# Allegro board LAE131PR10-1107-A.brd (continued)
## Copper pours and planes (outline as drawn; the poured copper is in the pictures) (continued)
GPU_B+ on BOTTOM (solid shape): 66.23,74.45 66.23,71.84 65.92,71.52 65.92,70.03 65.85,69.97 65.08,69.97 64.96,70.08 64.96,70.69 64.75,70.91 63.3,70.91 62.23,71.98 59.31,71.98 59.06,72.23 59.06,72.74 59.31,72.99 59.5,72.99 59.82,72.79 60.14,72.99 60.45,72.99 61.25,73.79 61.31,73.79 61.84,74.31 64.52,74.31 64.76,74.07 65.15,74.07 65.34,74.26 65.34,74.53 66.16,74.53
GPU_B+ on IN2 (solid shape): outline of 330 points within 54.28,64.07 65.14,74.35
GT_SNUB1 on TOP (solid shape): 71.9,72.6 71.9,71.81 71.74,71.66 70.11,71.66 69.92,71.85 68.77,71.85 68.75,71.88 68.75,72.57 68.91,72.74 71.76,72.74
GT_SNUB2 on BOTTOM (solid shape): 66.17,61.94 66.17,60.4 66.12,60.35 64.2,60.35 64.07,60.48 64.07,61.84 64.23,62.01 66.11,62.01
GT_SW1 on TOP (solid shape): 72,75.16 72,73.98 71.2,73.18 70.3,73.18 70,73.48 70,75.27 70.12,75.38 71.78,75.38
GT_SW1 on BOTTOM (solid shape): 74.75,75.47 74.75,74.28 74.64,74.16 72.19,74.16 72.13,74.1 72.13,73.42 72.2,73.35 74.63,73.35 74.87,73.11 74.87,72.14 74.64,71.91 69.17,71.91 68.84,72.24 68.84,74.49 68.89,74.54 71.16,74.54 72.18,75.56 74.67,75.56
GT_SW2 on BOTTOM (solid shape): 66.55,67.71 66.55,66.49 66.47,66.41 64.07,66.41 64,66.34 64,65.65 64.05,65.6 66.66,65.6 68.79,63.48 68.79,60.36 68.73,60.29 67.81,60.29 67.74,60.36 67.74,62.58 67.1,63.22 61.15,63.22 60.62,63.75 60.62,66.47 60.7,66.54 62.02,66.54 62.23,66.47 62.43,66.53 62.45,66.54 63.72,67.81 66.45,67.81
HP_OUT_L on TOP (solid shape): 303.97,27.02 303.97,25.7 303.86,25.6 302.96,25.6 302.87,25.68 302.87,26.95 303,27.07 303.91,27.07
HP_OUT_R on TOP (solid shape): 302.6,27.02 302.6,25.78 302.55,25.73 301.73,25.73 301.68,25.78 301.68,26.94 301.81,27.07 302.54,27.07
INT_SPK_L+ on TOP (solid shape): 301.47,11.12 301.47,8.57 301.39,8.48 300.53,8.48 300.5,8.52 300.5,10.01 300.41,10.1 300.41,11.28 300.47,11.35 301.25,11.35
INT_SPK_L+ on TOP (solid shape): 301.07,37.3 301.07,36.49 300.64,36.06 300.64,35.07 300.57,35.01 300.44,35.01 300.36,35.09 300.36,36.17 300.6,36.42 300.6,37.21 300.61,37.21 300.61,37.3 300.73,37.43 300.95,37.43
INT_SPK_L+ on IN1 (solid shape): 302.22,12.06 302.22,9.89 302.06,9.72 300.41,9.72 300.26,9.87 300.26,11.19 300.27,11.21 300.27,12.2 300.54,12.47 301.81,12.47
INT_SPK_L+ on IN1 (solid shape): 301.28,37.16 301.28,36.33 301.29,36.33 301.28,35.45 301.28,34.93 301.08,34.72 299.49,34.72 299.41,34.72 299.3,34.83 299.3,35.69 299.37,35.76 300.21,35.76 300.51,36.06 300.51,36.5 300.5,36.51 300.5,37.1 300.79,37.38 301.06,37.38
INT_SPK_L- on TOP (solid shape): 300.18,11.17 300.18,8.57 300.09,8.48 299.4,8.48 299.32,8.56 299.32,9.94 299,10.25 299,11.26 299.14,11.4 299.95,11.4
INT_SPK_L- on TOP (solid shape): 300.42,38.56 300.42,36.47 300.23,36.28 300.23,35.07 300.17,35 300.04,35 299.96,35.08 299.96,36.63 299.94,36.65 299.94,38.58 300.02,38.65 300.33,38.65
INT_SPK_L- on IN1 (solid shape): 299.75,11.68 299.75,10.04 299.52,9.81 298.27,9.81 298.13,9.95 298.13,11.83 298.25,11.94 299.48,11.94
INT_SPK_L- on IN1 (solid shape): 300.7,38.61 300.7,37.73 300.1,37.14 300.1,36.53 299.82,36.24 298.03,36.24 297.88,36.4 297.88,37.09 298.03,37.24 299.18,37.24 299.68,37.74 299.68,38.47 299.96,38.76 300.55,38.76
INT_SPK_R+ on TOP (solid shape): 297.41,12.11 297.41,10.99 296.38,9.96 296.38,8.64 296.28,8.54 295.54,8.54 295.44,8.64 295.44,10.37 296.29,11.22 296.29,12.13 296.39,12.24 297.28,12.24
INT_SPK_R+ on TOP (solid shape): 299.28,37.65 299.28,36.58 299.43,36.42 299.43,35.07 299.37,35.01 299.25,35.01 299.18,35.07 299.18,36.07 298.17,37.08 298.17,37.72 298.26,37.81 299.12,37.81
INT_SPK_R+ on IN3 (solid shape): 297.99,12.99 297.99,10.94 297.91,10.85 296.75,10.85 296.59,11.02 296.59,12.97 296.7,13.09 297.89,13.09
INT_SPK_R+ on IN3 (solid shape): 299.26,37.67 299.26,37.4 298.42,36.56 297.27,36.56 297.07,36.76 297.07,37.17 297.7,37.8 299.13,37.8
INT_SPK_R- on TOP (solid shape): 296.01,11.91 296.01,11.22 295.14,10.34 295.14,8.62 295.05,8.53 294.4,8.53 294.31,8.62 294.31,10.9 295.39,11.98 295.94,11.98
INT_SPK_R- on TOP (solid shape): 299.8,38.72 299.8,36.62 299.83,36.58 299.83,35.07 299.77,35.01 299.65,35.01 299.59,35.08 299.59,36.44 299.39,36.63 299.39,37.35 299.39,37.35 299.39,37.71 299,38.1 299,38.69 299.21,38.91 299.61,38.91
INT_SPK_R- on IN3 (solid shape): 295.82,13.54 295.82,11.07 295.48,10.72 294.64,10.72 294.46,10.9 294.46,12.74 294.72,13 294.72,13.4 295.01,13.68 295.68,13.68
INT_SPK_R- on IN3 (solid shape): 298.99,39.02 298.99,39.02 299.13,38.88 299.52,38.88 299.62,38.78 299.62,38.06 299.47,37.91 298.98,37.91 298.93,37.92 298.88,37.91 298.44,37.91 298.36,37.92 298.28,37.91 298.05,37.91 298.04,37.92 297.87,37.97 297.7,38 297.68,38 297.61,38.08 297.61,38.83 297.61,38.83 297.61,39.03 297.7,39.13 298.87,39.13
INT_SPKR_L+ on TOP (solid shape): 302.33,8.79 302.33,7.71 302.52,7.52 302.52,6.58 302.11,6.18 302.11,4.72 301.98,4.59 301.98,4.59 301.86,4.47 298.51,4.47 298.18,4.8 298.18,6 298.73,6.55 300.04,6.55 300.33,6.84 300.33,6.86 300.52,7.05 300.52,7.05 300.6,7.13 300.6,7.14 301.7,7.14 301.7,7.09 301.71,7.04 301.73,6.99 301.75,6.95 301.78,6.9 301.82,6.87 301.86,6.84 301.91,6.81 301.96,6.8 302.01,6.79 302.06,6.79 302.11,6.8 302.16,6.81 302.21,6.84 302.25,6.87 302.29,6.9 302.32,6.95 302.34,6.99 302.36,7.04 302.36,7.09 302.36,7.14 302.36,7.2 302.34,7.24 302.32,7.29 302.29,7.33 302.25,7.37 302.21,7.4 302.16,7.42 302.11,7.44 302.06,7.45 302.01,7.45 301.96,7.44 301.91,7.42 301.86,7.4 301.82,7.37 301.78,7.33 301.75,7.29 301.73,7.24 301.71,7.2 301.7,7.14 300.6,7.14 300.6,8.29 300.66,8.35 301.5,8.35 301.66,8.51 301.66,8.76 301.75,8.86 302.26,8.86
INT_SPKR_L+ on BOTTOM (solid shape): 298.95,10.43 298.95,10.1 299.05,10 302.07,10 303.3,8.77 303.3,7.8 303.11,7.61 301.94,7.61 301.77,7.78 301.77,8.45 301.32,8.9 299.3,8.9 299.19,9 297.78,9 297.62,9.17 297.62,10.59 297.76,10.73 298.65,10.73
INT_SPKR_L- on TOP (solid shape): 300.05,8.24 300.05,7.61 299.99,7.56 299.15,7.56 298.2,6.61 297.85,6.26 297.85,4.95 297.46,4.55 296.47,4.55 296.25,4.77 296.25,5.91 296.81,6.47 296.81,7.92 297.1,8.21 299.08,8.21 299.21,8.34 299.95,8.34
INT_SPKR_L- on BOTTOM (solid shape): 297.32,10.61 297.32,9.02 297.57,8.78 297.57,6.74 297.44,6.61 296.51,6.61 296.34,6.79 296.34,10.6 296.46,10.72 297.21,10.72
INT_SPKR_R+ on TOP (solid shape): 296.49,8.18 296.5,8.18 296.5,6.95 295.06,5.52 295.06,5 294.67,4.6 293.82,4.6 293.55,4.87 293.55,6.21 294.06,6.72 294.79,6.72 295.47,7.4 295.47,7.4 295.47,8.3 295.51,8.34 296.34,8.34
INT_SPKR_R+ on BOTTOM (solid shape): 296.08,10.55 296.08,6.68 295.89,6.5 295.39,6.5 295.15,6.74 295.15,10.51 295.35,10.71 295.91,10.71
INT_SPKR_R- on TOP (solid shape): 295.16,8.3 295.16,7.75 294.77,7.36 294.32,7.36 294.31,7.35 294.04,7.35 292.95,6.27 292.95,5.12 292.52,4.68 291.79,4.68 291.48,4.99 291.48,8.03 291.8,8.35 295.11,8.35
INT_SPKR_R- on BOTTOM (solid shape): 294.77,10.61 294.77,6.5 294.71,6.43 293.38,6.43 293.27,6.55 293.27,10.56 293.45,10.74 294.64,10.74
LG1_ISL88738 on TOP (solid shape): 64.26,89.76 64.26,89.25 64.01,88.99 63.63,88.99 63.38,89.25 60.96,89.25 60.1,88.39 59.72,88.39 58.8,87.47 58.8,85.82 58.68,85.69 58.3,85.69 58.04,85.95 58.04,88.36 59.06,89.38 59.44,89.38 60.2,90.14 63.88,90.14
LG1_ISL88738 on BOTTOM (solid shape): 63.66,90.24 63.66,90.23 64.21,89.67 64.21,89.62 64.26,89.57 64.26,89.25 64.14,89.12 63.76,89.12 63.38,89.5 62.99,89.5 62.87,89.63 62.87,90.39 63.5,90.39
LG2_ISL88738 on TOP (solid shape): 61.09,84.3 61.09,83.79 60.2,82.9 60.07,82.9 59.82,83.15 59.82,83.66 60.58,84.42 60.96,84.42
LG2_ISL88738 on BOTTOM (solid shape): 64.46,90.63 64.53,90.63 65.05,90.11 65.05,89.81 64.92,89.68 64.77,89.68 64.62,89.83 64.62,89.84 64.21,90.25 64.21,90.28 64.16,90.33 64.16,90.42 64.19,90.44 64.19,90.69 64.05,90.83 64.03,90.83 63.93,90.93 63.27,90.93 63.25,90.95 63.25,91.13 63.97,91.13
LG2_ISL88738 on IN3 (solid shape): 65.09,90.52 65.09,89.25 64.96,89.12 64.33,89.12 64.18,89.27 64.19,89.3 64.21,89.48 64.14,89.64 64.14,90.52 64.26,90.65 64.96,90.65
LG2_ISL88738 on IN3 (solid shape): 61.09,84.3 61.09,83.66 60.74,83.31 60.67,83.25 60.61,83.18 60.39,82.96 60.01,82.96 59.88,83.09 59.88,83.91 59.93,83.97 59.95,83.97 60.18,84.06 60.28,84.29 60.28,84.31 60.45,84.49 60.9,84.49
LX1_ISL88738 on TOP (solid shape): 57.79,88.36 57.79,82.14 57.03,81.37 55.12,81.37 54.76,81.74 54.76,85.95 54.17,86.54 53.88,86.54 53.8,86.62 53.8,87.19 53.93,87.32 53.93,88.22 54.24,88.54 54.34,88.54 54.55,88.75 54.55,88.84 54.75,89.04 57.1,89.04
LX1_ISL88738 on BOTTOM (solid shape): 58.93,86.2 58.93,81.63 58.42,81.12 55.25,81.12 54.99,81.37 54.99,86.57 54.87,86.69 53.78,86.69 53.62,86.85 53.62,87.1 53.92,87.1 54.1,87.27 57.86,87.27
LX1_ISL88738 on BOTTOM (solid shape): 62.66,90.29 62.66,89.66 62.68,89.64 62.68,89.59 63.27,88.99 64.26,88.99 64.39,88.87 64.39,87.85 64.26,87.72 63.12,87.72 62.87,87.98 62.87,88.88 62.86,88.89 62.86,89.08 62.46,89.48 62.46,90.26 62.51,90.32 62.64,90.32
LX1_ISL88738 on IN3 (solid shape): 58.68,87.09 58.68,86.52 58.36,86.2 57.45,86.2 57.3,86.36 57.3,87.16 57.42,87.28 58.49,87.28
LX1_ISL88738 on IN3 (solid shape): 63.27,90.12 63.23,90.08 63.16,89.76 63.4,89.54 63.44,89.53 63.44,88.17 63.25,87.98 62.87,87.98 62.74,88.11 62.74,88.2 62.75,88.3 62.74,88.39 62.74,88.78 62.75,88.87 62.74,88.96 62.74,89.12 62.42,89.44 62.42,90.07 62.55,90.2 63.18,90.2
LX2_ISL88738 on TOP (solid shape): 64.14,87.72 64.14,86.62 64.13,86.58 64.14,86.58 64.14,83.91 62.45,82.23 62.45,79.97 62.2,79.72 60.14,79.72 59.95,79.92 59.95,82.01 60.2,82.27 60.2,82.65 61.34,83.79 61.34,87.6 61.6,87.85 64.01,87.85
LX2_ISL88738 on BOTTOM (solid shape): 64.9,85.82 64.9,81.37 63.5,79.98 60.45,79.98 60.07,80.36 60.07,81.25 60.33,81.5 60.33,82.72 60.84,83.23 60.84,85.5 61.6,86.26 64.45,86.26
LX2_ISL88738 on BOTTOM (solid shape): 64.22,91.39 64.26,91.36 64.59,91.03 64.62,91 64.72,90.9 66.17,90.9 66.42,90.65 66.42,89.88 66.17,89.63 65.41,89.63 65.15,89.88 65.15,90.16 64.71,90.61 64.58,90.73 64.51,90.73 64.16,91.08 64.16,91.09 64.11,91.16 64.04,91.21 64.03,91.21 63.91,91.33 63.3,91.33 63.25,91.38 63.25,91.48 63.3,91.53 64.09,91.53
LX2_ISL88738 on IN3 (solid shape): 66.55,90.77 66.55,89.5 66.17,89.12 66.17,86.58 62.76,83.17 62.76,82.69 62.46,82.39 62.09,82.39 61.25,83.23 61.25,83.67 61.56,83.98 62.12,83.98 65.41,87.27 65.41,90.77 65.66,91.03 66.3,91.03
LX_1.8VALW on BOTTOM (solid shape): 165.66,103.03 165.66,102.2 165.43,101.97 164.44,101.97 164.24,101.77 164.24,101.31 163.94,101.01 163.48,101.01 163.35,100.88 163.35,100.13 163.29,100.07 162.66,100.07 162.66,100.27 162.26,100.67 162.26,103.88 162.49,104.11 164.58,104.11
LX_1V_PRIM on BOTTOM (solid shape): 172.82,110.3 172.82,109.36 172.82,109.29 173.41,108.71 173.41,107.69 173.34,107.62 169.76,107.62 169.36,108.03 169.36,108.7 169.44,108.78 170.44,108.78 170.64,108.98 171.66,108.98 172.06,109.38 172.06,110.26 172.14,110.34 172.78,110.34
LX_1VS_VCCIO on BOTTOM (solid shape): 183.75,113.48 183.75,111.02 183.94,110.83 185.14,110.83 185.21,110.76 185.21,110.08 185.17,110.04 184.05,110.04 183.68,109.67 182.81,109.67 182.63,109.85 182.63,113.46 182.73,113.56 183.67,113.56
LX_3V on TOP (solid shape): 232.16,23.08 232.16,21.56 231.9,21.3 229.24,21.3 228.73,21.81 228.73,23.08 228.98,23.34 231.9,23.34
LX_3V on BOTTOM (solid shape): 233.52,27.92 233.52,27.26 233.44,27.18 232.64,27.18 231.79,26.33 231.79,22.62 231.46,22.29 228.98,22.29 228.86,22.42 228.86,27.37 229.22,27.73 230.86,27.73 230.86,27.68 230.87,27.63 230.88,27.58 230.91,27.53 230.94,27.49 230.97,27.45 231.01,27.42 231.06,27.4 231.11,27.38 231.16,27.37 231.21,27.37 231.27,27.38 231.31,27.4 231.36,27.42 231.4,27.45 231.44,27.49 231.47,27.53 231.49,27.58 231.51,27.63 231.52,27.68 231.52,27.73 231.51,27.78 231.49,27.83 231.47,27.88 231.44,27.92 231.4,27.96 231.36,27.99 231.31,28.01 231.27,28.03 231.21,28.03 231.16,28.03 231.11,28.03 231.06,28.01 231.01,27.99 230.97,27.96 230.94,27.92 230.91,27.88 230.88,27.83 230.87,27.78 230.86,27.73 229.22,27.73 229.66,28.17 230.61,28.17 231.08,28.64 231.08,29.13 231.37,29.41 232.03,29.41
LX_5V on TOP (solid shape): 38.61,50.84 38.61,48.66 38.34,48.39 33.98,48.39 32.88,49.5 32.88,51.06 33.38,51.56 37.89,51.56
LX_5V on BOTTOM (solid shape): 38.5,50.95 38.5,47.58 38.46,47.54 37.4,47.54 37.03,47.17 36.25,47.17 36.17,47.09 35.59,47.09 35.5,47.18 35.5,49.07 35.36,49.21 33.3,49.21 33.15,49.36 33.15,51.28 33.26,51.39 38.06,51.39
LX_DDR on BOTTOM (solid shape): 36.34,34.79 36.34,32.12 36.83,31.63 36.83,29.29 36.67,29.13 30.2,29.13 29.66,29.67 29.66,30.89 29.92,31.16 31.54,31.16 31.73,31.35 31.73,32.18 31.71,32.19 31.83,32.3 34.43,32.3 34.75,32.62 34.75,34.63 34.93,34.8 36.32,34.8
LX_VCC_EDRAM on TOP (solid shape): 55.5,58.66 55.5,56.94 54.67,56.11 52.92,56.11 52.55,56.49 52.55,57.99 52.38,58.16 51.45,58.16 51.34,58.27 51.34,58.95 51.41,59.02 55.13,59.02
LX_VCC_EOPIO on TOP (solid shape): 54.11,47.65 54.11,47.28 54.13,47.26 54.13,45.5 53.89,45.26 51.46,45.26 51.31,45.41 51.31,46.72 50.87,47.17 50.67,47.17 50.67,47.16 49.89,47.16 49.8,47.26 49.8,47.85 49.91,47.95 53.8,47.95
Net_83 on TOP (solid shape): 285.18,105.38 277.18,105.38 277.18,113.38 285.18,113.38
Net_83 on TOP (solid shape): 300.61,92.23 292.61,92.23 292.61,100.23 300.61,100.23
Net_84 on TOP (solid shape): 264.53,90.96 254.53,90.96 254.53,105.96 264.53,105.96
PBATT+_C on BOTTOM (solid shape): 215.26,36.49 215.73,36.49 218.77,33.45 218.77,31.35 218.47,31.04 214.92,31.04 214.72,31.25 214.72,33.2 214.73,33.22 213.44,34.51 211.11,34.51 210.9,34.73 210.9,36.28 211.13,36.51 215.24,36.51
PWM1_GT on BOTTOM (solid shape): 66.22,76.99 66.22,75.6 66.11,75.48 65.41,75.48 65.27,75.62 65.27,77.02 65.43,77.18 66.03,77.18
RING2 on TOP (solid shape): 303.48,19.53 303.48,18.2 303.29,18 302.52,18 302.4,18.12 302.4,19.53 302.53,19.65 303.35,19.65
RING2 on TOP (solid shape): 299.82,29.75 299.82,28.83 299.22,28.22 299.22,27.93 299.01,27.71 299.01,27.17 298.97,27.13 298.39,27.13 298.33,27.2 298.33,27.3 298.07,27.56 298.07,28.18 298.07,28.24 298.23,28.4 299.04,28.4 299.61,28.97 299.61,29.76 299.67,29.82 299.76,29.82
RING2 on BOTTOM (solid shape): 299.15,29.3 299.15,27.97 299.09,27.91 298.2,27.91 298.07,28.03 298.07,29.37 298.26,29.56 298.9,29.56
RING2 on BOTTOM (solid shape): 304.29,20.48 304.29,19.8 304.21,19.71 304.15,19.61 304.14,19.6 303.53,18.99 303.53,18.57 303,18.04 302.35,18.04 302.2,18.19 302.2,19.59 302.9,20.29 302.9,20.48 303.02,20.61 304.17,20.61
RING2_R on TOP (solid shape): 307.91,19.01 309.84,19.01 309.89,18.96 309.89,17.73 309.82,17.66 306.73,17.66 305.97,18.42 303.85,18.42 303.74,18.54 303.74,19.5 303.88,19.63 307.29,19.63
RING2_R on IN3 (solid shape): 309.2,18.92 309.2,17.48 308.94,17.23 306.11,17.23 305.93,17.41 305.93,19.11 306.05,19.22 308.89,19.22
SA_SNUB on TOP (solid shape): 78.37,90.14 78.37,87.48 78.17,87.28 77.16,87.28 76.97,87.47 76.97,90.26 77.03,90.32 78.19,90.32
SA_SW on TOP (solid shape): 72.12,88.27 72.12,87.14 72.02,87.04 70.79,87.04 70.71,87.12 70.71,88.29 70.82,88.4 71.99,88.4
SA_SW on TOP (solid shape): 81.37,89.91 81.37,89.17 81.93,88.6 81.93,86.67 81.71,86.45 79.76,86.45 79.03,87.18 79,87.27 78.94,87.35 78.94,89.58 79.59,90.23 81.05,90.23
SA_SW on BOTTOM (solid shape): 82.06,89.24 82.06,88.29 81.08,88.29 81.08,87.48 82.06,87.48 82.06,86.68 81.83,86.44 79.78,86.44 79.02,87.2 76.18,87.2 76.08,87.31 76.08,88.19 76.15,88.27 78.75,88.27 80.08,89.59 81.71,89.59
SA_SW on IN2 (solid shape): 71.78,88.7 71.78,87.24 71.63,87.09 70.78,87.09 70.56,87.31 70.56,88.79 70.77,88.99 71.49,88.99
SA_SW on IN2 (solid shape): 79.17,88.96 79.17,88.43 79.48,88.12 79.48,87.52 79.11,87.15 78.48,87.15 78.26,87.37 78.26,88.86 78.46,89.06 79.07,89.06
SLEEVE on TOP (solid shape): 303.57,21.96 303.57,20.15 303.46,20.03 302.26,20.03 302.14,20.16 302.14,22 302.33,22.19 303.34,22.19
SLEEVE on TOP (solid shape): 300.22,29.76 300.22,28.68 300.42,28.48 300.42,27.84 300.36,27.78 300.1,27.78 299.89,27.57 299.89,27.13 299.87,27.1 299.26,27.1 299.18,27.18 299.18,27.74 299.32,27.88 299.33,27.89 299.33,28.06 299.99,28.72 299.99,29.75 300.07,29.82 300.17,29.82
SLEEVE on BOTTOM (solid shape): 300.87,27.97 300.87,26.76 300.74,26.64 299.53,26.64 299.4,26.76 299.4,27.87 299.41,28.04 299.47,28.1 300.74,28.1
SLEEVE on BOTTOM (solid shape): 302.03,23.57 302.03,23.55 302.12,23.29 302.38,23.19 302.4,23.2 302.71,22.89 302.71,20.65 302.64,20.58 302.64,20.54 302.48,20.38 301.28,20.38 301.18,20.48 301.18,22.32 300.87,22.64 300.87,23.46 301.12,23.72 301.88,23.72
SLEEVE_R on TOP (solid shape): 309.92,21.92 309.92,20.84 309.81,20.73 307.66,20.73 307.04,20.11 303.87,20.11 303.77,20.21 303.77,20.99 303.81,21.03 304.43,21.03 304.44,21.03 305.26,21.03 306.23,22.01 309.83,22.01
SLEEVE_R on IN1 (solid shape): 309.5,22.88 309.5,21.16 309.37,21.04 307.47,21.04 307.37,21.14 307.37,22.75 307.56,22.94 309.44,22.94
SNB_+1VALWP on TOP (solid shape): 184.47,95.83 184.47,94.28 184.09,93.9 181.24,93.9 180.94,94.2 180.94,95.81 181.28,96.16 184.14,96.16
SNUB_1.8VALW on BOTTOM (solid shape): 164.15,98.76 163.94,98.56 162.9,98.56 162.66,98.8 162.66,99.69 163.44,99.69 163.67,99.91 164.15,99.91
SNUB_CHG1 on TOP (solid shape): 52.89,90.21 52.89,89.51 53.21,89.19 53.64,89.19 53.72,89.11 53.72,87.34 53.7,87.32 52.32,87.32 52.09,87.55 52.09,90.22 52.14,90.26 52.83,90.26
SNUB_CHG2 on TOP (solid shape): 61.98,79.47 61.98,78.71 61.34,78.07 61.34,77.06 61.09,76.8 60.33,76.8 60.07,77.06 60.07,79.34 60.33,79.6 61.85,79.6
SW_+1VALWP on TOP (solid shape): 185.23,99.09 185.23,96.7 185.04,96.51 182.5,96.51 182.42,96.59 182.42,97.53 183.06,98.17 183.06,98.59 182.88,98.77 182.88,99.47 182.92,99.51 184.81,99.51
SW_+1VALWP on BOTTOM (solid shape): 185.19,99.22 185.19,98.09 185.37,97.91 185.9,97.91 187.01,96.81 188.69,96.81 188.93,96.56 188.93,93.69 188.57,93.34 186.06,93.34 185.4,94 185.4,95.93 183.94,97.39 183.94,99.19 184.05,99.31 185.1,99.31
UG1_ISL88738 on TOP (solid shape): 53.47,86.89 53.47,85.95 52.96,85.44 52.2,85.44 51.82,85.82 51.82,86.71 52.17,87.06 53.29,87.06
UG1_ISL88738 on BOTTOM (solid shape): 62.28,90.29 62.28,89.45 62.74,88.99 62.74,88.21 62.61,88.08 62.26,88.08 62.18,88.16 62.18,88.94 62.08,89.05 62.08,90.29 62.13,90.34 62.23,90.34
UG1_ISL88738 on IN2 (solid shape): 62.74,88.99 62.74,88.04 62.68,87.98 61.91,87.98 61.72,88.17 61.72,88.99 61.85,89.12 62.61,89.12
UG1_ISL88738 on IN2 (solid shape): 53.62,88.3 53.62,87.67 53.47,87.52 53.47,86.59 53.3,86.43 52.53,86.43 52.29,86.66 52.29,87.69 53.04,88.44 53.48,88.44
UG2_ISL88738 on TOP (solid shape): 66.99,84.23 66.99,82.84 66.68,82.52 66.11,82.52 65.92,82.71 65.92,83.53 66.04,83.66 66.04,84.17 66.23,84.36 66.87,84.36
UG2_ISL88738 on BOTTOM (solid shape): 64.5,91.84 64.54,91.84 65.08,91.31 65.08,91.13 64.95,91 64.8,91 64.09,91.71 63.25,91.71 63.2,91.76 63.2,91.87 63.27,91.94 64.4,91.94
UG2_ISL88738 on IN2 (solid shape): 66.29,84.71 66.49,84.51 66.49,82.58 66.42,82.52 65.79,82.52 65.66,82.64 65.66,84.42 65.97,84.73 66.29,84.73
UG2_ISL88738 on IN2 (solid shape): 65.86,91.29 65.86,90.83 65.79,90.76 65.79,90.01 65.41,90.01 65.09,90.33 65.09,90.65 64.22,91.52 64.22,91.74 64.47,92 65.14,92
VID0_EDRAM_VR on TOP (solid shape): 48.75,61.57 48.75,60.08 49.19,59.64 49.19,59.31 49.08,59.21 47.63,59.21 47.08,59.76 47.08,61.64 47.17,61.72 48.6,61.72
N16399089 on BOTTOM (solid shape): 68.96,103.09 68.96,101.95 68.71,101.69 67.42,101.69 67.19,101.93 66.16,101.93 65.93,101.69 65.4,101.69 65.37,101.72 64.62,101.72 64.39,101.95 64.39,103.09 64.65,103.35 68.71,103.35
N16775513 on BOTTOM (solid shape): 31.78,33.43 31.78,32.61 31.07,31.89 31.07,31.32 31.02,31.27 30.35,31.27 30.31,31.31 30.31,32.68 31.09,33.46 31.75,33.46
N16775517 on BOTTOM (solid shape): 34.52,33.5 34.52,33.38 34.38,33.24 34.3,33.24 33.59,32.53 32.49,32.53 32.45,32.57 32.45,33.42 32.49,33.45 33.69,33.45 33.81,33.57 34.44,33.57
N16783126 on BOTTOM (solid shape): 233.56,26.51 233.56,25.83 233.42,25.69 233.42,24.95 232.99,24.53 232.99,22.72 233,22.72 233,22.59 233.19,22.4 233.19,21.32 232.92,21.05 232.16,21.05 231.9,21.3 231.9,22.07 232.32,22.48 232.32,26.25 232.63,26.55 233.51,26.55
N16783223 on BOTTOM (solid shape): 33.21,49.04 33.93,49.04 34.89,48.08 34.89,47.15 34.83,47.08 34.24,47.08 34.17,47.16 34.17,47.67 33.62,48.22 33.09,48.22 32.85,48.46 31.92,48.46 31.76,48.61 31.76,49.52 31.84,49.6 32.65,49.6
N16784595 on BOTTOM (solid shape): 230.71,30.6 230.71,29.64 230.83,29.52 230.83,28.6 230.65,28.42 229.09,28.42 228.92,28.59 228.92,30.36 229.43,30.86 230.45,30.86
N16784799 on BOTTOM (solid shape): 39.98,48.38 39.98,46.41 39.8,46.23 39.26,46.23 39.18,46.31 39.18,48.51 39.23,48.56 39.8,48.56
N17370862 on BOTTOM (solid shape): outline of 113 points within 42.04,84.8 46.89,89.62
N17377163 on TOP (solid shape): 195.99,23.04 195.99,22.73 195.89,22.63 195.17,22.63 195.14,22.6 195.07,22.6 194.66,22.19 193.83,22.19 193.59,21.95 193.59,21.41 193.49,21.31 192.78,21.31 192.62,21.47 192.62,22.7 192.91,22.99 194.35,22.99 194.49,23.12 194.55,23.12 194.55,23.12 195.9,23.12
N18026694 on TOP (solid shape): 53.34,107.08 53.34,106.52 53.72,106.14 54.1,106.14 54.23,106.01 54.23,105.76 54.1,105.63 51.82,105.63 51.55,105.9 51.55,107.04 51.73,107.22 53.2,107.22
N18150673 on TOP (solid shape): outline of 146 points within 37.59,101.63 47.89,105.35
N18150689 on TOP (solid shape): 37.85,101.63 37.85,100.17 38.1,99.92 38.1,98.52 38.08,98.5 37.36,98.5 37.09,98.77 36.45,98.77 36.26,98.96 36.26,101.89 36.58,102.2 37.28,102.2
N18670418 on BOTTOM (solid shape): 64.52,87.22 64.52,86.96 64.26,86.71 61.22,86.71 61.09,86.84 61.09,87.34 61.22,87.47 64.26,87.47
N24606174 on TOP (solid shape): 187.39,99.22 186.18,98.01 185.49,98.01 185.36,98.14 185.36,99.22 185.8,99.66 185.8,99.79 186.59,100.58 186.59,100.78 186.69,100.88 187.39,100.88
N28712229 on TOP (solid shape): 65.25,75.71 65.25,75.16 65.08,74.99 64.77,74.99 64.49,74.71 63.88,74.71 63.86,74.73 63.86,75.53 63.87,75.61 63.86,75.7 63.86,75.77 64.01,75.93 65.04,75.93
N28712232 on TOP (solid shape): 65.19,74.58 65.19,73.86 64.84,73.5 63.88,73.5 63.83,73.55 63.83,74.39 64.45,74.39 64.77,74.71 65.06,74.71
N28712235 on TOP (solid shape): 63.22,75.54 63.24,75.47 63.24,73.69 63,73.45 62.42,73.45 62.3,73.57 62.3,75.57 62.46,75.73 63.02,75.73
N28718526 on TOP (solid shape): 73.68,90.22 73.68,88.28 73.68,88.27 73.68,87.44 73.56,87.32 73.53,87.33 73.36,87.35 73.2,87.28 72.95,87.28 72.94,87.28 72.83,87.32 72.71,87.31 72.68,87.3 72.54,87.44 72.54,88.35 72.74,88.54 72.74,90.27 72.87,90.39 73.51,90.39
N28769860 on BOTTOM (solid shape): 185.64,114.46 185.64,111.59 185.57,111.52 185.14,111.52 184.86,111.8 184.86,111.85 184.72,111.99 184.72,112.68 184.86,112.82 184.86,114.64 184.91,114.69 185.41,114.69
N28771761 on BOTTOM (solid shape): 185.46,107.45 185.46,106.85 185.36,106.75 183.96,106.75 183.89,106.83 183.89,107.75 184.03,107.89 185.02,107.89
N30191541 on TOP (solid shape): 48.61,46.38 48.61,45.35 48.2,44.94 48.05,44.94 48.05,44.9 47.9,44.9 47.78,45.02 47.78,45.25 47.94,45.41 48.13,45.41 48.37,45.64 48.37,46.39 48.43,46.44 48.54,46.44
N32011565 on BOTTOM (solid shape): 73.79,87.94 73.79,87.46 73.67,87.34 73.67,86.9 73.52,86.76 73.35,86.76 73.35,86.76 73.3,86.76 73.22,86.84 73.22,86.88 73.14,86.96 73.14,87.24 72.96,87.41 72.96,88.02 73.05,88.11 73.62,88.11
N32011565 on IN2 (solid shape): 73.52,87.31 73.66,87.18 73.66,86.83 73.81,86.68 75.26,86.68 75.34,86.76 75.4,86.76 75.52,86.87 75.52,87.17 75.64,87.29 76.29,87.29 76.39,87.19 76.39,86.35 76.2,86.16 73.56,86.16 73.14,86.58 73.14,87.24 73.22,87.31 73.52,87.31
N45640623 on TOP (solid shape): 277.93,56.98 279.03,56.98 279.2,56.81 279.2,56.36 279.12,56.27 276.05,56.27 275.87,56.45 275.87,57.25 276.02,57.39 277.52,57.39
N132000604 on BOTTOM (solid shape): 67.19,91.92 67.19,89.76 67.06,89.63 66.68,89.63 66.55,89.76 66.55,91.92 66.68,92.04 67.06,92.04

Small or netless copper shapes (teardrops, artwork), in the pictures only: 105 on TOP, 47 on BOTTOM, 2 on GND1, 18 on IN1, 3 on IN2, 2 on IN3

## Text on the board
Ref Des/Silkscreen Bottom: A | H7 | H8 | 3 | M2X5 | DIMM A | DDR4 | EDP | TS | IR | Rev:1.0(A00) | CAZ20 LA-E131P | 2016-11-08 | Made In Taiwan | N4WX7 | REV:A00 | PWB P/N: | ALL RIGHT RESERVED | COPYRIGHT 2016 | DIMM B | BATTERY | TP | 2 | USH | LTE | WWAN | SPEAKER | RTC | 1 | LED | DC-IN | FAN | WLAN | WIGIG | BT | HF | Pb | e1
User.Comments: LA-E131P | 2016-11-08 | 2017-11-08 | CAZ20 | Win
BODY_CENTER: +TBTA_VBUS | +TBTA_VBUS_1 | +VCC_EOPIO | +3.3V_ALW | +VCC_GT | +3V_RUN | +VCC_CORE | +5V_VLW | +VCC_SA | +5V_RUN | +1.0V_PRIM | +1.0VS_VCCIO | +3.3V_ALW_PCH | +3.3V_RUN | GNDA
COMPVAL_TYPE_BOTTOM: L7 | L8 | IN3
User.42: trace Width | 7.2mil | 7.4mil | 4.4mil | 4.7mil | 4.9mil | 5.3mil | Width/space | 4.4 / 3.7 | 4.9 / 3.5 | 4.1 / 3.8 | 4.7 / 3.9 | 5.3 / 4.2 | 4.4 / 6 | 4.7 / 5.3 | 4.9 / 6.8 | 5.3 / 5.9 | 3.5 / 6.4 | 3.5 / 4.6 | 3.5 / 4.1 | L2/L4 | L4/L7 | L2 | L7 | 4.6mil | 4.6 / 3.7 | 6.9 / 3.5 | L5/L7 | L3 | L6 | 1_0mm-8L_160420 | L1-TOP | L2-GND1 | L3-IN1 | L4-VCC | L5-IN2 | L6-IN3 | L7-GND2 | L8-BOT | LAYER | NAME | STACKUP: 8 LAYER | 39 ohm | 50 ohm | THICKNESS=1.0mm | 82 ohm | 85 ohm | 90 ohm | 100 ohm | Ref
User.44: FIGURE | SIZE | 8.0 | 16.0 | 20.0 | 22.0 | 28.0 | 35.0 | 39.0 | 91.0 | 98.0 | 126.0 | 130.0 | 146.0 | 30.0 | 31.0 | 43.0 | 45.0 | 63.0 | 65.0 | 71.0 | 47.0x16.0 | 55.0x24.0 | 55.0x28.0 | 57.0x24.0 | 63.0x24.0 | 63.0x31.0 | 67.0x28.0 | 71.0x28.0 | 94.0x28.0 | 94.0x43.0 | 138.0x98.0 | 185.0x146.0 | 197.0x157.0 | 37.0x28.0 | DRILL CHART: TOP to BOTTOM | ALL UNITS ARE IN MILS | TOLERANCE | +3.0/-3.0 | +2.0/-2.0 | PLATED | NON-PLATED | QTY | 6611 | 12 | 33 | 19 | 27 | 10 | 5 | 8 | 2 | 4 | 1 | 7
